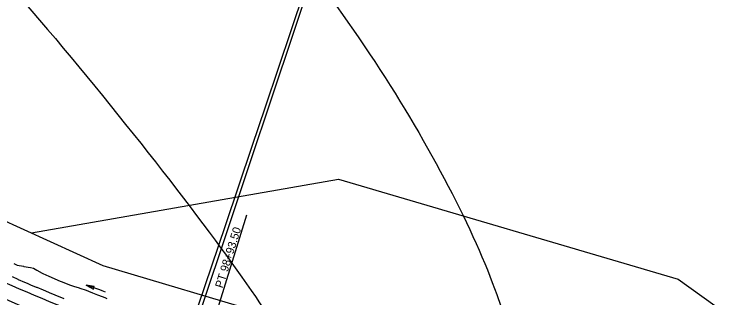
# Model space of a CAD drawing. Extents: x 1 to 1477871, y 1 to 1872901.
# Drawn here: x 1443501 to 1444024, y 1855108 to 1855316 of the extents above; entities that cross this region are included whole.
import ezdxf

# ---------------------------------------------------------------- set-up
doc = ezdxf.new("R2010")
doc.units = 0
for name, color, linetype in [('R_Floodplain', 7, 'Continuous'), ('R_Horz Alg', 7, 'Continuous'), ('R_Horz Alg Annot', 7, 'Continuous'), ('R_Proposed Const Limits_Fill', 7, 'Continuous'), ('R_Proposed Road_Lane', 7, 'Continuous'), ('R_Proposed Road_Shoulder', 7, 'Continuous'), ('R_ROW', 7, 'Continuous'), ('R_Temp Easement', 7, 'Continuous'), ('R_Water', 7, 'Continuous')]:
    doc.layers.add(name, color=color, linetype=linetype)

msp = doc.modelspace()

# ---------------------------------------------------------------- linework, layer by layer
at = {"layer": 'R_Floodplain'}
for points in [[(1444534.23, 1857777.84), (1444398.78, 1857609.12), (1444367.89, 1857131.47), (1444306.1, 1856808.28), (1444134.95, 1856378.26), (1444024.62, 1856227.92), (1443837.91, 1855964.82), (1443664.53, 1855852.06), (1443479.03, 1855867.82), (1443335.96, 1855886.01), (1443298.37, 1855854.49), (1443356.57, 1855756.28), (1443606.51, 1855482.27), (1443757.19, 1855307.33), (1443863.11, 1855113.58), (1443878.59, 1855007.91), (1443849.87, 1854910.07), (1443760.66, 1854753.08), (1443429.28, 1854512.04), (1443240.87, 1854371.16), (1443115.26, 1854254.04), (1443060.94, 1853889.1), (1443099.99, 1853680.31), (1443032.09, 1853386.66), (1443001.54, 1853198.25), (1444534.23, 1857777.84), (1443001.54, 1853198.25)], [(1442151.14, 1856970.74), (1442271.17, 1856854.35), (1442333.01, 1856625.2), (1442433.64, 1856208.12), (1442553.67, 1856042.02), (1442997.42, 1855782.56), (1443193.84, 1855637.06), (1443334.48, 1855500.06), (1443473.91, 1855372.75), (1443683.66, 1855109.66), (1443730.06, 1855020.65), (1443721.27, 1854972.23), (1443705.74, 1854932.59), (1443621.79, 1854821.68), (1443387.16, 1854639.56), (1443131.33, 1854479.52), (1443010.09, 1854397.07), (1442954.32, 1854286.74), (1442894.91, 1853873.3), (1442881.57, 1853521.69), (1442881.57, 1853348.32), (1442151.14, 1856970.74), (1442881.57, 1853348.32)]]:
    msp.add_open_spline(points, degree=3, dxfattribs=at)
at = {"layer": 'R_Horz Alg'}
msp.add_arc((1444035.38, 1856341.58), 1348.14, 233.78664, 252.76667, dxfattribs=at)
msp.add_arc((1444035.38, 1856341.58), 1348.14, 233.78664, 252.76667, dxfattribs=at)
at = {"layer": 'R_Horz Alg Annot'}
msp.add_lwpolyline([(1443635.98, 1855053.96), (1443671.53, 1855168.57)], dxfattribs=at)
at = {"layer": 'R_Proposed Const Limits_Fill'}
msp.add_lwpolyline([(1443500.36, 1855132.87), (1443502.87, 1855131.76), (1443507.43, 1855130.84), (1443507.79, 1855130.77), (1443512.73, 1855129.85), (1443514.77, 1855129.45), (1443517.28, 1855128.05), (1443521.17, 1855125.89), (1443521.58, 1855125.66), (1443525.99, 1855123.5), (1443527.77, 1855122.77), (1443530.52, 1855121.64), (1443534.52, 1855120.02), (1443535.05, 1855119.8), (1443539.6, 1855117.99), (1443541.29, 1855117.33), (1443541.91, 1855117.09), (1443544.23, 1855116.36), (1443548.26, 1855115.11), (1443548.92, 1855114.91), (1443553.52, 1855113.24), (1443555.09, 1855112.59), (1443558.05, 1855111.39), (1443561.85, 1855109.86), (1443562.59, 1855109.56), (1443567.17, 1855107.83), (1443568.67, 1855107.31)], dxfattribs=at)
at = {"layer": 'R_Proposed Road_Lane'}
for radius, start in [(1359.14, 240.29296), (1337.14, 244.54295)]:
    msp.add_arc((1444035.38, 1856341.58), radius, start, 252.76667, dxfattribs=at)
at = {"layer": 'R_Proposed Road_Shoulder'}
msp.add_lwpolyline([(1443499.12, 1855123.24), (1443503.31, 1855121.4), (1443503.64, 1855121.26), (1443508.17, 1855119.29), (1443510.06, 1855118.48), (1443512.71, 1855117.34), (1443516.82, 1855115.6), (1443517.25, 1855115.41), (1443521.81, 1855113.5), (1443523.6, 1855112.75), (1443526.36, 1855111.6), (1443530.39, 1855109.95), (1443530.93, 1855109.73), (1443535.5, 1855107.86), (1443537.2, 1855107.18)], dxfattribs=at)
at = {"layer": 'R_ROW'}
for p, q in [((1443335.78, 1855236.23), (1443565.8, 1855131.35)), ((1443565.8, 1855131.35), (1443949.34, 1855017.73))]:
    msp.add_line(p, q, dxfattribs=at)
at = {"layer": 'R_Temp Easement'}
for p, q in [((1443513.24, 1855155.31), (1443738.83, 1855194.81)), ((1443738.83, 1855194.81), (1443988.19, 1855121.34)), ((1443988.19, 1855121.34), (1444040.86, 1855083.67))]:
    msp.add_line(p, q, dxfattribs=at)
at = {"layer": 'R_Water'}
for p, q in [((1443553.47, 1855117.05), (1443558.76, 1855114.02)), ((1443559.48, 1855116.01), (1443553.47, 1855117.05)), ((1443558.76, 1855114.02), (1443559.48, 1855116.01))]:
    msp.add_line(p, q, dxfattribs=at)
msp.add_lwpolyline([(1443567.59, 1855111.98), (1443565.22, 1855112.83), (1443563.45, 1855113.47), (1443560.53, 1855114.51), (1443555.84, 1855116.2), (1443553.47, 1855117.05)], dxfattribs=at)

# ---------------------------------------------------------------- texts
at = {"layer": 'R_Horz Alg Annot'}
msp.add_text('PT 98+93.50', height=6, rotation=72.7667, dxfattribs=at).set_placement((1443653.68, 1855114.41))

doc.saveas('drawing.dxf')
